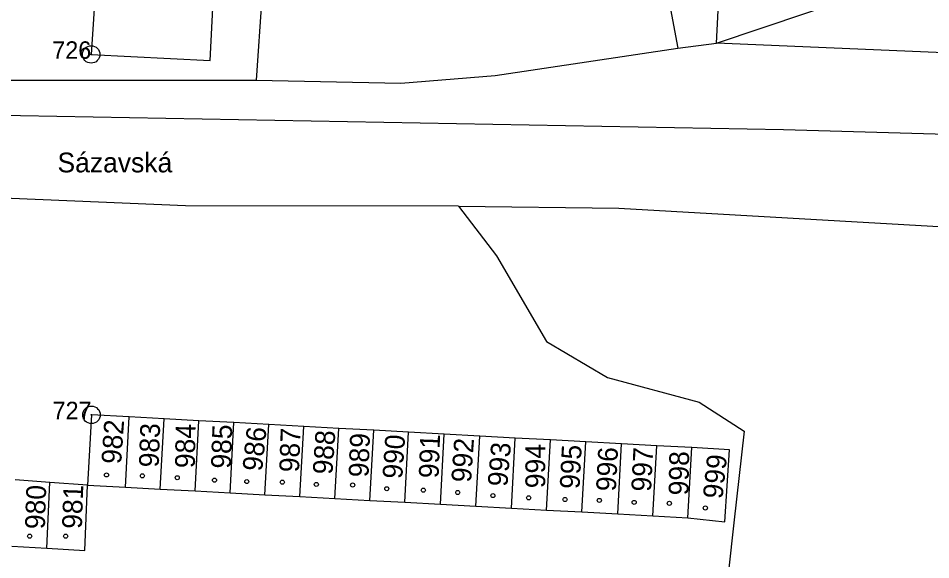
# Model space of a CAD drawing. Extents: x -680203 to -673936, y -1102717 to -1093650.
# Drawn here: x -679434.2 to -679355.9, y -1098597 to -1098550.5 of the extents above; entities that cross this region are included whole.
import ezdxf

# ---------------------------------------------------------------- set-up
doc = ezdxf.new("R2010")
doc.units = 0
for name, color, linetype in [('SOxx02xx_Koleje_param další_Popis10', 7, 'Continuous'), ('SOxx02xx_Staničení_Popis10', 7, 'Continuous'), ('SOxxxxxx_Koleje_param další_Popis10', 7, 'Continuous'), ('SOxxxxxx_Osa_bod_P', 7, 'Continuous'), ('x_prac', 7, 'Continuous')]:
    doc.layers.add(name, color=color, linetype=linetype)

msp = doc.modelspace()

# ---------------------------------------------------------------- linework, layer by layer
at = {"layer": 'SOxx02xx_Koleje_param další_Popis10'}
for centre, radius in [((-679427.97, -1098553.62), 0.75), ((-679427.97, -1098553.62), 0.03), ((-679427.94, -1098584.59), 0.75), ((-679427.94, -1098584.59), 0.03)]:
    msp.add_circle(centre, radius, dxfattribs=at)
at = {"layer": 'SOxxxxxx_Koleje_param další_Popis10'}
for centre in [(-679426.647, -1098589.749), (-679423.567, -1098589.829), (-679420.577, -1098589.989), (-679417.377, -1098590.199), (-679414.607, -1098590.319), (-679411.557, -1098590.369), (-679408.637, -1098590.569), (-679405.517, -1098590.619), (-679402.587, -1098590.939), (-679399.447, -1098591.059), (-679396.497, -1098591.259), (-679393.477, -1098591.529), (-679390.407, -1098591.719), (-679387.287, -1098591.859), (-679384.337, -1098591.939), (-679381.347, -1098592.109), (-679378.327, -1098592.189), (-679375.237, -1098592.589), (-679433.247, -1098595.009), (-679430.157, -1098595.009)]:
    msp.add_circle(centre, 0.175, dxfattribs=at)
at = {"layer": 'x_prac'}
for p, q in [((-679411.73, -1098525.43), (-679413.79, -1098555.84)), ((-679374.27, -1098552.65), (-679320.38, -1098534.45)), ((-679374.27, -1098552.65), (-679373.69, -1098540.67)), ((-679377.59, -1098553.07), (-679374.27, -1098552.65)), ((-679338.89, -1098554.17), (-679374.27, -1098552.65)), ((-679447.62, -1098555.83), (-679413.79, -1098555.84)), ((-679425.03, -1098590.79), (-679424.7, -1098584.77)), ((-679421.7, -1098584.93), (-679424.7, -1098584.77)), ((-679422.03, -1098590.96), (-679421.7, -1098584.93)), ((-679418.71, -1098585.09), (-679421.7, -1098584.93)), ((-679419.04, -1098591.12), (-679418.71, -1098585.09)), ((-679415.72, -1098585.26), (-679418.71, -1098585.09)), ((-679416.04, -1098591.28), (-679415.72, -1098585.26)), ((-679412.72, -1098585.42), (-679415.72, -1098585.26)), ((-679413.05, -1098591.45), (-679412.72, -1098585.42)), ((-679409.71, -1098585.58), (-679412.72, -1098585.42)), ((-679410.04, -1098591.61), (-679409.71, -1098585.58)), ((-679406.71, -1098585.75), (-679409.71, -1098585.58)), ((-679407.04, -1098591.78), (-679406.71, -1098585.75)), ((-679403.71, -1098585.91), (-679406.71, -1098585.75)), ((-679404.04, -1098591.94), (-679403.71, -1098585.91)), ((-679400.72, -1098586.08), (-679403.71, -1098585.91)), ((-679401.05, -1098592.1), (-679400.72, -1098586.08)), ((-679397.65, -1098586.24), (-679400.72, -1098586.08)), ((-679397.98, -1098592.27), (-679397.65, -1098586.24)), ((-679394.61, -1098586.41), (-679397.65, -1098586.24)), ((-679394.94, -1098592.44), (-679394.61, -1098586.41)), ((-679391.56, -1098586.58), (-679394.61, -1098586.41)), ((-679391.88, -1098592.6), (-679391.56, -1098586.58)), ((-679388.54, -1098586.74), (-679391.56, -1098586.58)), ((-679388.87, -1098592.77), (-679388.54, -1098586.74)), ((-679385.51, -1098586.91), (-679388.54, -1098586.74)), ((-679385.84, -1098592.93), (-679385.51, -1098586.91)), ((-679382.43, -1098587.07), (-679385.51, -1098586.91)), ((-679382.76, -1098593.1), (-679382.43, -1098587.07)), ((-679379.41, -1098587.24), (-679382.43, -1098587.07)), ((-679379.74, -1098593.27), (-679379.41, -1098587.24)), ((-679376.41, -1098587.4), (-679379.41, -1098587.24)), ((-679376.74, -1098593.43), (-679376.41, -1098587.4)), ((-679431.51, -1098590.39), (-679434.5, -1098590.17)), ((-679431.77, -1098596.05), (-679431.51, -1098590.39)), ((-679425.03, -1098590.79), (-679422.03, -1098590.96)), ((-679422.03, -1098590.96), (-679419.04, -1098591.12)), ((-679419.04, -1098591.12), (-679416.04, -1098591.28)), ((-679416.04, -1098591.28), (-679413.05, -1098591.45)), ((-679413.05, -1098591.45), (-679410.04, -1098591.61)), ((-679410.04, -1098591.61), (-679407.04, -1098591.78)), ((-679407.04, -1098591.78), (-679404.04, -1098591.94)), ((-679404.04, -1098591.94), (-679401.05, -1098592.1)), ((-679401.05, -1098592.1), (-679397.98, -1098592.27)), ((-679397.98, -1098592.27), (-679394.94, -1098592.44)), ((-679394.94, -1098592.44), (-679391.88, -1098592.6)), ((-679391.88, -1098592.6), (-679388.87, -1098592.77)), ((-679388.87, -1098592.77), (-679385.84, -1098592.93)), ((-679385.84, -1098592.93), (-679382.76, -1098593.1)), ((-679382.76, -1098593.1), (-679379.74, -1098593.27)), ((-679379.74, -1098593.27), (-679376.74, -1098593.43)), ((-679434.78, -1098595.88), (-679431.77, -1098596.05))]:
    msp.add_line(p, q, dxfattribs=at)
for points in [[(-679382.68, -1098527.59), (-679382.73, -1098530.92), (-679379.12, -1098538.61), (-679380.32, -1098538.65), (-679380.37, -1098537.28), (-679382.17, -1098537.35), (-679382.12, -1098538.72), (-679391.01, -1098539.06), (-679390.59, -1098548.41), (-679384.96, -1098548.12), (-679384.95, -1098548.32), (-679380.23, -1098548.07), (-679380.56, -1098545.8), (-679378.99, -1098545.57), (-679377.59, -1098553.07)], [(-679424.15, -1098540.22), (-679427.09, -1098540.07), (-679427.97, -1098553.62), (-679417.75, -1098554.14), (-679417.05, -1098540.58), (-679420.71, -1098540.39), (-679420.64, -1098538.91), (-679424.08, -1098538.73), (-679424.15, -1098540.22)], [(-679413.79, -1098555.84), (-679401.39, -1098556.1), (-679393.29, -1098555.43), (-679377.59, -1098553.07)], [(-679224.46, -1098567.17), (-679258.68, -1098565.34), (-679278.74, -1098563.33), (-679311.75, -1098562.64), (-679339.5, -1098560.92), (-679368.52, -1098560.1), (-679477.74, -1098558.09), (-679478.16, -1098555.47)], [(-679396.42, -1098566.65), (-679419.86, -1098566.63), (-679434.82, -1098565.99), (-679495.54, -1098565.13), (-679495.61, -1098567.06), (-679505.61, -1098567)], [(-679396.42, -1098566.65), (-679382.65, -1098566.82), (-679339.23, -1098569.31)], [(-679396.42, -1098566.65), (-679393.18, -1098570.93), (-679388.88, -1098578.28), (-679383.65, -1098581.39), (-679375.77, -1098583.51), (-679371.91, -1098585.99), (-679372.78, -1098593.86), (-679373.24, -1098598.02), (-679371.38, -1098602.71)], [(-679424.7, -1098584.77), (-679427.94, -1098584.59), (-679428.27, -1098590.62), (-679425.03, -1098590.79)], [(-679376.74, -1098593.43), (-679373.56, -1098593.77), (-679373.16, -1098587.58), (-679376.41, -1098587.4)], [(-679431.77, -1098596.05), (-679428.52, -1098596.24), (-679428.27, -1098590.62), (-679431.51, -1098590.39)]]:
    msp.add_lwpolyline(points, dxfattribs=at)

# ---------------------------------------------------------------- texts
at = {"layer": 'SOxx02xx_Koleje_param další_Popis10'}
for s, p in [('726', (-679431.306, -1098553.995)), ('727', (-679431.276, -1098584.965))]:
    msp.add_text(s, height=1.5, dxfattribs=at).set_placement(p)
at = {"layer": 'SOxx02xx_Staničení_Popis10'}
msp.add_text('Sázavská', height=1.7, dxfattribs=at).set_placement((-679430.86, -1098563.755))
at = {"layer": 'SOxxxxxx_Osa_bod_P'}
for s, rotation, p in [('982', 86, (-679425.397, -1098588.855)), ('983', 88, (-679422.171, -1098589.124)), ('984', 89, (-679419.068, -1098589.178)), ('985', 88, (-679415.981, -1098589.234)), ('986', 84, (-679413.294, -1098589.484)), ('987', 88, (-679410.121, -1098589.544)), ('988', 86, (-679407.257, -1098589.755)), ('989', 88, (-679404.161, -1098589.974)), ('990', 86, (-679401.267, -1098590.125)), ('991', 88, (-679398.141, -1098590.054)), ('992', 86, (-679395.357, -1098590.435)), ('993', 85, (-679392.241, -1098590.8)), ('994', 90, (-679388.985, -1098590.89)), ('995', 87, (-679386.044, -1098590.99)), ('996', 87, (-679382.924, -1098591.19)), ('997', 87, (-679379.904, -1098591.22)), ('998', 89, (-679376.688, -1098591.518)), ('999', 84, (-679373.764, -1098591.854)), ('980', 88, (-679431.951, -1098594.434)), ('981', 88, (-679428.771, -1098594.404))]:
    msp.add_text(s, height=1.7, rotation=rotation, dxfattribs=at).set_placement(p)

doc.saveas('drawing.dxf')
